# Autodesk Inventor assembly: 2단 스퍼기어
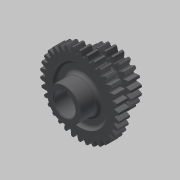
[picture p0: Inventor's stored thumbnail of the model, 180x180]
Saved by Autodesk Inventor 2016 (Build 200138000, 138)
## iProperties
Created: 2018-09
Part Number: 2단 스퍼기어
Document SubType Name: Assembly
Designer: MYS
Mass: 385.382 g
Surface Area: 216.679 cm^2
Volume: 48.1727 cm^3
Density: 8 g/cm^3
Author: MYS
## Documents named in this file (4)
- C:\Users\MYS\Desktop\답안\2단 스퍼기어.iam
- C:\Users\MYS\Desktop\답안\2단 스퍼기어.ipt
- C:\Users\MYS\Desktop\답안\2단 스퍼기어\디자인 액셀러레이터\스퍼 기어1.iam
- C:\Users\MYS\Desktop\답안\2단 스퍼기어\디자인 액셀러레이터\스퍼 기어2.iam
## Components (1 placed, 1 different names)
1. 2단 스퍼기어:1
